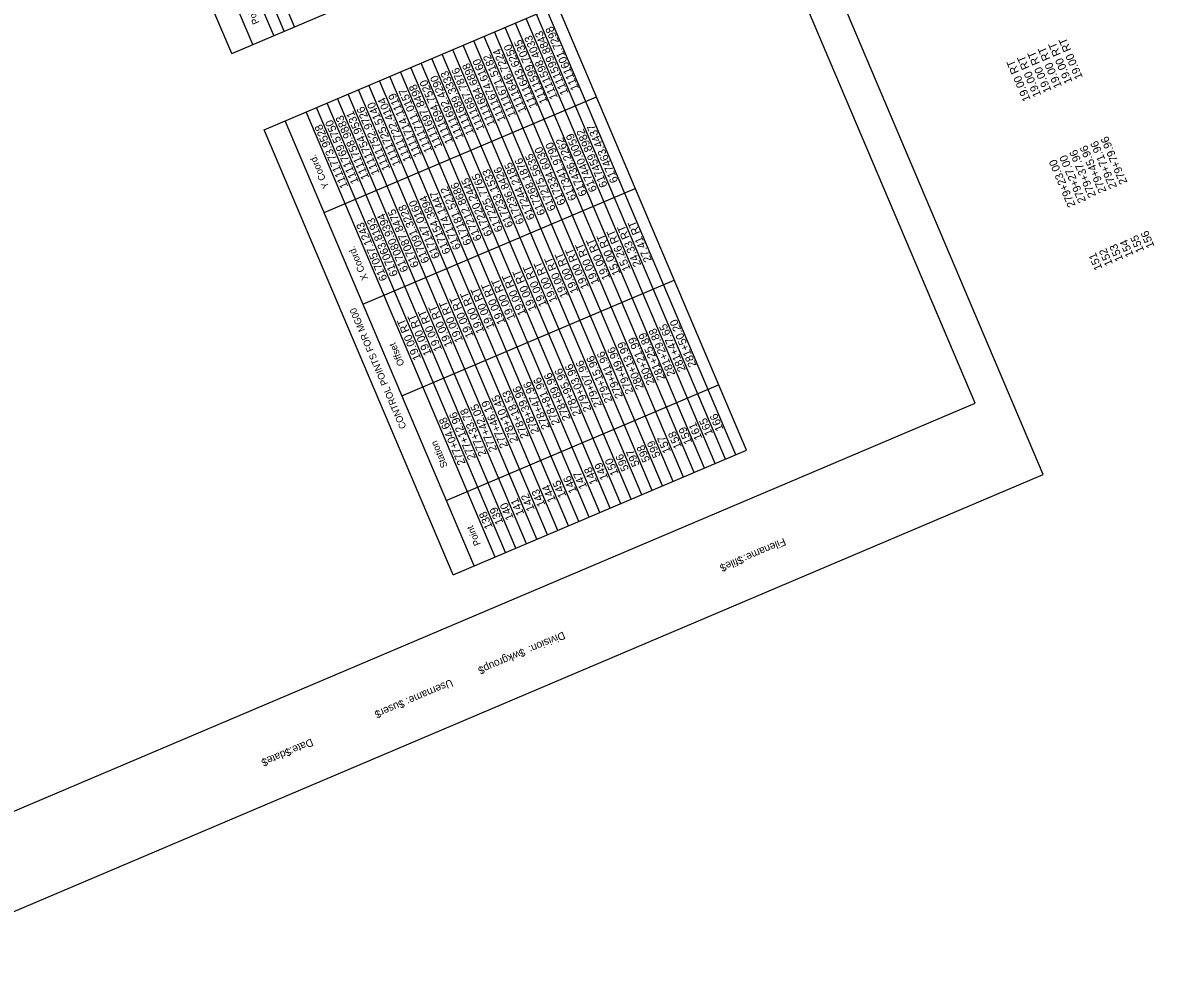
# Model space of a CAD drawing. Extents: x 1111260 to 1112147, y 617053 to 618212.
# Drawn here: x 1111649.5 to 1112146.8, y 617053.2 to 617466.6 of the extents above; entities that cross this region are included whole.
import ezdxf

# ---------------------------------------------------------------- set-up
doc = ezdxf.new("R2010")
doc.units = 0
for name, color, linetype in [('ANNOTATION', 7, 'Continuous'), ('BORDER', 7, 'Continuous'), ('H_V CONTROLS', 7, 'Continuous'), ('PLOT BOUNDARY', 7, 'Continuous')]:
    doc.layers.add(name, color=color, linetype=linetype)

msp = doc.modelspace()

# ---------------------------------------------------------------- linework, layer by layer
at = {"layer": 'BORDER'}
for p, q in [((1112068.1, 617299.33), (1111755.51, 618035.74)), ((1111584.83, 617094.2), (1112068.1, 617299.33))]:
    msp.add_line(p, q, dxfattribs=at)
at = {"layer": 'H_V CONTROLS'}
for p, q in [((1111769.06, 617464.81), (1111686.03, 617660.41)), ((1111759.85, 617460.9), (1111676.82, 617656.51)), ((1111764.46, 617462.85), (1111681.43, 617658.46)), ((1111750.65, 617456.99), (1111667.62, 617652.6)), ((1111741.44, 617453.08), (1111658.41, 617648.69)), ((1111755.69, 617419.53), (1111884.56, 617474.23)), ((1111962.98, 617276.67), (1111879.95, 617472.28)), ((1111967.59, 617278.63), (1111884.56, 617474.23)), ((1111967.59, 617278.63), (1111884.56, 617474.23)), ((1111741.44, 617453.08), (1111782.87, 617470.67)), ((1111949.18, 617270.81), (1111866.15, 617466.42)), ((1111953.78, 617272.77), (1111870.75, 617468.37)), ((1111958.38, 617274.72), (1111875.35, 617470.33)), ((1111939.97, 617266.9), (1111856.94, 617462.51)), ((1111944.57, 617268.86), (1111861.54, 617464.47)), ((1111926.16, 617261.04), (1111843.13, 617456.65)), ((1111930.77, 617263), (1111847.74, 617458.6)), ((1111935.37, 617264.95), (1111852.34, 617460.56)), ((1111916.96, 617257.14), (1111833.93, 617452.74)), ((1111921.56, 617259.09), (1111838.53, 617454.7)), ((1111903.15, 617251.27), (1111820.12, 617446.88)), ((1111907.75, 617253.23), (1111824.72, 617448.84)), ((1111912.36, 617255.18), (1111829.33, 617450.79)), ((1111889.34, 617245.41), (1111806.31, 617441.02)), ((1111893.95, 617247.37), (1111810.92, 617442.97)), ((1111898.55, 617249.32), (1111815.52, 617444.93)), ((1111880.14, 617241.51), (1111797.11, 617437.11)), ((1111884.74, 617243.46), (1111801.71, 617439.07)), ((1111781.99, 617383.17), (1111901.65, 617433.96)), ((1111866.33, 617235.65), (1111783.3, 617431.25)), ((1111870.93, 617237.6), (1111787.9, 617433.21)), ((1111875.54, 617239.55), (1111792.51, 617435.16)), ((1111857.13, 617231.74), (1111774.1, 617427.35)), ((1111861.73, 617233.69), (1111778.7, 617429.3)), ((1111847.92, 617227.83), (1111764.89, 617423.44)), ((1111838.72, 617223.92), (1111755.69, 617419.53)), ((1111799.08, 617342.89), (1111918.75, 617393.69)), ((1111816.17, 617302.62), (1111935.84, 617353.42)), ((1111835.71, 617256.6), (1111955.38, 617307.39)), ((1111838.72, 617223.92), (1111967.59, 617278.63))]:
    msp.add_line(p, q, dxfattribs=at)
at = {"layer": 'PLOT BOUNDARY'}
msp.add_lwpolyline([(1112097.99, 617268.06), (1111765.87, 618050.49), (1111259.59, 617835.59), (1111591.71, 617053.16)], close=True, dxfattribs=at)

# ---------------------------------------------------------------- texts
at = {"layer": 'ANNOTATION'}
for s, height, p in [('1111598.4033', 3.5156, (1111884.77, 617433.68)), ('1111599.8843', 3.5156, (1111889.41, 617435.65)), ('1111601.7298', 3.5156, (1111894.06, 617437.62)), ('1111643.6250', 3.5156, (1111875.74, 617429.85)), ('1111599.7035', 3.5156, (1111880.31, 617431.79)), ('19.00 RT', 3.516, (1112110.9, 617440.59)), ('19.00 RT', 3.516, (1112115.48, 617442.53)), ('1111671.5182', 3.45, (1111866.37, 617425.87)), ('1111646.7224', 3.5156, (1111870.97, 617427.82)), ('19.00 RT', 3.516, (1112097.16, 617434.75)), ('19.00 RT', 3.516, (1112101.71, 617436.69)), ('19.00 RT', 3.516, (1112106.29, 617438.63)), ('1111687.7876', 3.45, (1111852.52, 617419.99)), ('1111684.6898', 3.45, (1111857.2, 617421.98)), ('1111674.6160', 3.45, (1111861.8, 617423.93)), ('19.00 RT', 3.516, (1112092.56, 617432.8)), ('1111694.7520', 3.5156, (1111838.77, 617414.16)), ('1111692.4290', 3.5156, (1111843.39, 617416.12)), ('1111689.3333', 3.5156, (1111847.96, 617418.06)), ('1111711.0157', 3.5156, (1111829.62, 617410.27)), ('1111697.8498', 3.5156, (1111834.08, 617412.17)), ('1111725.5140', 3.5156, (1111815.74, 617404.38)), ('1111722.4104', 3.5156, (1111820.4, 617406.36)), ('1111714.1119', 3.5156, (1111824.97, 617408.3)), ('1111754.9531', 3.5156, (1111806.48, 617400.45)), ('1111752.9726', 3.5156, (1111811.09, 617402.41)), ('1111773.9528', 3.5156, (1111792.64, 617394.57)), ('1111769.5750', 3.5156, (1111797.29, 617396.55)), ('1111758.9883', 3.5156, (1111801.87, 617398.49)), ('617436.2262', 3.5156, (1111897.58, 617391.11)), ('617440.0059', 3.5156, (1111902.04, 617393.01)), ('617459.8982', 3.5156, (1111906.67, 617394.97)), ('617463.4437', 3.5156, (1111911.32, 617396.95)), ('279+79.96', 3.516, (1112135.06, 617396.39)), ('617334.6030', 3.5156, (1111888.24, 617387.15)), ('617341.9790', 3.5156, (1111893, 617389.17)), ('279+45.96', 3.516, (1112125.87, 617392.49)), ('279+71.96', 3.516, (1112130.49, 617394.44)), ('617268.1876', 3.45, (1111879.31, 617382.68)), ('617275.5635', 3.45, (1111883.88, 617384.62)), ('279+23.00', 3.516, (1112112.31, 617386.28)), ('279+27.00', 3.516, (1112116.9, 617388.23)), ('279+37.96', 3.516, (1112121.3, 617390.54)), ('617233.1533', 3.5156, (1111865.23, 617377.38)), ('617236.8426', 3.45, (1111870.03, 617378.74)), ('617244.2185', 3.45, (1111874.71, 617380.73)), ('617212.8686', 3.5156, (1111851.35, 617371.49)), ('617220.2445', 3.5156, (1111856.04, 617373.48)), ('617225.7765', 3.5156, (1111860.65, 617375.44)), ('617174.1447', 3.5156, (1111842.24, 617367.62)), ('617181.5212', 3.5156, (1111846.89, 617369.6)), ('617091.3228', 3.5156, (1111828.36, 617361.73)), ('617147.0160', 3.5156, (1111833.01, 617363.71)), ('617154.3894', 3.5156, (1111837.66, 617365.68)), ('617080.9394', 3.5156, (1111819.13, 617357.81)), ('617087.8475', 3.5156, (1111823.75, 617359.77)), ('617057.1243', 3.5156, (1111809.9, 617353.9)), ('617063.8193', 3.5156, (1111814.55, 617355.87)), ('24.33 RT', 3.516, (1111921.44, 617360.17)), ('27.41 RT', 3.516, (1111926.1, 617362.14)), ('15.00 RT', 3.516, (1111912.35, 617356.31)), ('15.26 RT', 3.516, (1111916.81, 617358.2)), ('155', 3.516, (1112142.4, 617366.38)), ('156', 3.516, (1112146.98, 617368.32)), ('19.00 RT', 3.45, (1111898.41, 617350.39)), ('19.00 RT', 3.516, (1111903.01, 617352.34)), ('19.00 RT', 3.516, (1111907.78, 617354.37)), ('152', 3.516, (1112128.65, 617360.55)), ('153', 3.516, (1112133.21, 617362.48)), ('154', 3.516, (1112137.79, 617364.42)), ('19.00 RT', 3.45, (1111889.24, 617346.5)), ('19.00 RT', 3.45, (1111893.84, 617348.45)), ('151', 3.516, (1112124.06, 617358.6)), ('19.00 RT', 3.516, (1111875.43, 617340.63)), ('19.00 RT', 3.516, (1111880, 617342.58)), ('19.00 RT', 3.45, (1111884.56, 617344.51)), ('19.00 RT', 3.516, (1111861.66, 617334.79)), ('19.00 RT', 3.516, (1111866.12, 617336.69)), ('19.00 RT', 3.516, (1111870.81, 617338.68)), ('19.00 RT', 3.516, (1111852.44, 617330.88)), ('19.00 RT', 3.516, (1111857.01, 617332.82)), ('19.00 RT', 3.516, (1111838.52, 617324.97)), ('19.00 RT', 3.516, (1111843.13, 617326.93)), ('19.00 RT', 3.516, (1111847.78, 617328.9)), ('19.00 RT', 3.516, (1111829.33, 617321.07)), ('19.00 RT', 3.516, (1111833.91, 617323.01)), ('19.00 RT', 3.516, (1111824.68, 617319.09)), ('281+29.88', 3.516, (1111936.4, 617312.06)), ('281+47.65', 3.516, (1111941.03, 617314.02)), ('281+50.20', 3.516, (1111945.68, 617316)), ('280+21.99', 3.516, (1111927.36, 617308.22)), ('281+25.89', 3.516, (1111931.94, 617310.16)), ('279+41.96', 3.45, (1111913.43, 617302.31)), ('279+49.96', 3.45, (1111917.99, 617304.24)), ('280+13.99', 3.516, (1111922.6, 617306.2)), ('279+07.96', 3.45, (1111904.15, 617298.37)), ('279+15.96', 3.45, (1111908.82, 617300.35)), ('278+89.96', 3.516, (1111890.4, 617292.53)), ('278+95.96', 3.516, (1111895.01, 617294.49)), ('279+03.96', 3.516, (1111899.59, 617296.43)), ('278+39.96', 3.516, (1111876.6, 617286.67)), ('278+47.96', 3.516, (1111881.25, 617288.65)), ('278+81.96', 3.516, (1111885.71, 617290.54)), ('278+10.45', 3.516, (1111867.37, 617282.76)), ('278+18.53', 3.516, (1111872.02, 617284.73)), ('277+33.78', 3.516, (1111853.49, 617276.87)), ('277+42.05', 3.516, (1111858.11, 617278.82)), ('277+46.19', 3.516, (1111862.88, 617280.4)), ('277+04.68', 3.516, (1111844.27, 617272.95)), ('277+12.96', 3.516, (1111848.75, 617275.3)), ('165', 3.516, (1111952.94, 617285.96)), ('166', 3.516, (1111957.59, 617287.94)), ('158', 3.516, (1111939.27, 617280.16)), ('159', 3.516, (1111943.85, 617282.1)), ('161', 3.516, (1111948.31, 617284)), ('599', 3.45, (1111929.9, 617276.18)), ('157', 3.516, (1111934.51, 617278.14)), ('596', 3.45, (1111916.06, 617270.31)), ('597', 3.45, (1111920.73, 617272.29)), ('598', 3.45, (1111925.34, 617274.25)), ('149', 3.516, (1111906.93, 617266.43)), ('150', 3.516, (1111911.5, 617268.37)), ('146', 3.516, (1111893.16, 617260.59)), ('147', 3.516, (1111897.62, 617262.48)), ('148', 3.516, (1111902.31, 617264.47)), ('144', 3.516, (1111883.93, 617256.67)), ('145', 3.516, (1111888.51, 617258.61)), ('141', 3.516, (1111870.02, 617250.76)), ('142', 3.516, (1111874.63, 617252.72)), ('143', 3.516, (1111879.28, 617254.7)), ('139', 3.516, (1111860.83, 617246.86)), ('140', 3.516, (1111865.4, 617248.8)), ('138', 3.516, (1111856.18, 617244.89))]:
    msp.add_text(s, height=height, rotation=113, dxfattribs=at).set_placement(p)
at = {"layer": 'BORDER'}
for s, p in [('Filename:', (1111984.02, 617240.21)), ('$file$', (1111965.49, 617232.34)), ('Division:', (1111887.06, 617199.05)), ('$wkgroup$', (1111869.55, 617191.62)), ('Username:', (1111837.8, 617178.14)), ('$user$', (1111816.52, 617169.11)), ('$date$', (1111766.75, 617147.98)), ('Date:', (1111776.36, 617152.06))]:
    msp.add_text(s, height=3.348, rotation=203, dxfattribs=at).set_placement(p)
at = {"layer": 'H_V CONTROLS'}
for s, p in [('Point', (1111753.63, 617466.6)), ('Y Coord.', (1111784.29, 617394.37)), ('X Coord.', (1111801.39, 617354.1)), ('CONTROL POINTS FOR MG00', (1111818.24, 617288.8)), ('Offset', (1111817.38, 617316.42)), ('Station', (1111836.36, 617271.69)), ('Point', (1111850.9, 617237.44))]:
    msp.add_text(s, height=3, rotation=113, dxfattribs=at).set_placement(p)

doc.saveas('drawing.dxf')
